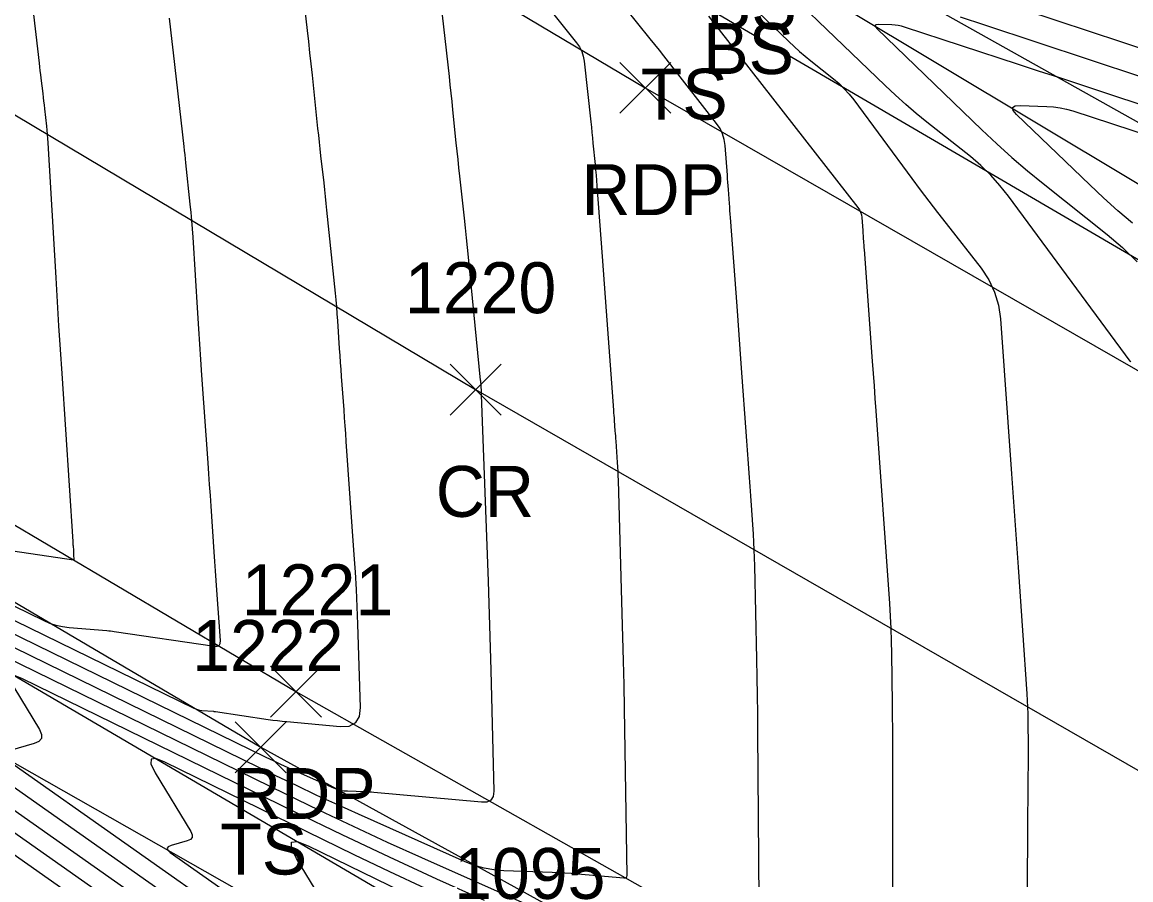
# Model space of a CAD drawing. Extents: x 1650836 to 1652450, y 332578 to 333908.
# Drawn here: x 1651871 to 1651914.59, y 332889.77 to 332923.46 of the extents above; entities that cross this region are included whole.
import ezdxf

# ---------------------------------------------------------------- set-up
doc = ezdxf.new("R2010")
doc.units = 0
for name, color, linetype in [('L_A', 7, 'Continuous'), ('L_I', 7, 'Continuous'), ('L_TIC', 7, 'Continuous'), ('LELB', 7, 'Continuous'), ('LSOGCMA', 7, 'Continuous'), ('LSOGCMI', 7, 'Continuous'), ('P_A', 7, 'Continuous'), ('P_I', 7, 'Continuous'), ('P_TIC', 7, 'Continuous'), ('PET', 7, 'Continuous'), ('PRC', 7, 'Continuous')]:
    doc.layers.add(name, color=color, linetype=linetype)

msp = doc.modelspace()

# ---------------------------------------------------------------- linework, layer by layer
at = {"layer": 'L_TIC'}
for points in [[(1651879.379, 332893.976), (1651881.379, 332895.976)], [(1651881.379, 332893.976), (1651879.379, 332895.976)]]:
    msp.add_lwpolyline(points, dxfattribs=at)
at = {"layer": 'LELB'}
for points in [[(1652004.611, 332876.377), (1652000.575, 332878.245), (1651971.943, 332890.057), (1651931.469, 332910.231), (1651899.444, 332928.179), (1651868.914, 332946.877)], [(1652004.611, 332876.377), (1652004.078, 332874.687), (1651998.585, 332874.498), (1651971.102, 332887.818), (1651930.139, 332907.952), (1651899.336, 332926.423), (1651867.782, 332944.676)], [(1651863.072, 332944.289), (1651896.914, 332924.632), (1651933.94, 332903.012), (1651966.422, 332886.181), (1652000.17, 332869.987)], [(1651844.759, 332915.941), (1651880.379, 332894.976), (1651917.082, 332874.787), (1651949.824, 332853.945), (1651967.074, 332844.342), (1652000.53, 332828.254), (1652035.357, 332809.776), (1652067.23, 332793.489), (1652106.029, 332773.108), (1652143.274, 332753.324), (1652172.167, 332734.049)], [(1652048.756, 332662.461), (1652082.555, 332678.298), (1652130.366, 332703.201), (1652148.083, 332715.406), (1652159.47, 332726.367), (1652148.02, 332734.227), (1652128.413, 332739.339), (1652116.951, 332747.33), (1652106.793, 332756.875), (1652094.604, 332761.138), (1652083.802, 332764.466), (1652074.482, 332770.284), (1652065.17, 332770.428), (1652062.989, 332774.387), (1652054.537, 332784.724), (1652034.993, 332796.475), (1652025.062, 332801.1), (1652009.772, 332808.074), (1651988.967, 332816.401), (1651980.006, 332832.954), (1651960.575, 332843.477), (1651932.852, 332862.75), (1651890.753, 332886.019), (1651847.527, 332911.35)], [(1651992.104, 332790.093), (1651989.915, 332804.738), (1651988.967, 332816.401), (1651977.078, 332830.976), (1651959.162, 332840.786), (1651931.328, 332859.703), (1651889.406, 332883.733), (1651845.231, 332908.813)]]:
    msp.add_lwpolyline(points, dxfattribs=at)
at = {"layer": 'LSOGCMA'}
msp.add_lwpolyline([(1651850.934, 332910.157), (1651871.822, 332899.963), (1651872.07, 332899.856), (1651872.324, 332899.774), (1651872.585, 332899.715), (1651872.852, 332899.681), (1651874.331, 332899.562), (1651874.404, 332899.555), (1651874.477, 332899.547), (1651874.55, 332899.538), (1651874.622, 332899.528), (1651878.561, 332898.943), (1651878.672, 332898.942), (1651878.749, 332898.979), (1651878.791, 332899.053), (1651878.799, 332899.164), (1651878.652, 332901.151), (1651878.625, 332901.525), (1651878.598, 332901.9), (1651878.572, 332902.274), (1651878.547, 332902.649), (1651878.427, 332904.447), (1651878.399, 332904.871), (1651878.37, 332905.295), (1651878.341, 332905.72), (1651878.311, 332906.144), (1651878.069, 332909.598), (1651878.027, 332910.205), (1651877.987, 332910.811), (1651877.947, 332911.417), (1651877.908, 332912.024), (1651877.721, 332915.012), (1651877.699, 332915.337), (1651877.674, 332915.662), (1651877.645, 332915.986), (1651877.612, 332916.31), (1651877.44, 332917.938), (1651877.423, 332918.096), (1651877.406, 332918.254), (1651877.388, 332918.412), (1651877.37, 332918.57), (1651876.946, 332922.249), (1651876.893, 332922.704), (1651876.841, 332923.16), (1651876.79, 332923.615)], dxfattribs=at)
at = {"layer": 'LSOGCMI'}
for points in [[(1651858.348, 332905.977), (1651877.745, 332896.511), (1651877.821, 332896.478), (1651877.899, 332896.453), (1651877.979, 332896.435), (1651878.062, 332896.424), (1651878.517, 332896.388), (1651878.54, 332896.386), (1651878.562, 332896.383), (1651878.584, 332896.381), (1651878.607, 332896.377), (1651880.674, 332896.07), (1651880.856, 332896.044), (1651881.039, 332896.021), (1651881.221, 332896.001), (1651881.404, 332895.983), (1651883.503, 332895.792), (1651883.861, 332895.81), (1651884.113, 332895.942), (1651884.259, 332896.185), (1651884.299, 332896.542), (1651884.197, 332899.811), (1651884.172, 332900.493), (1651884.141, 332901.175), (1651884.103, 332901.857), (1651884.058, 332902.538), (1651883.745, 332906.987), (1651883.723, 332907.297), (1651883.7, 332907.607), (1651883.678, 332907.917), (1651883.655, 332908.227), (1651883.558, 332909.541), (1651883.538, 332909.814), (1651883.518, 332910.087), (1651883.499, 332910.361), (1651883.481, 332910.634), (1651883.408, 332911.728), (1651883.389, 332912.001), (1651883.367, 332912.274), (1651883.343, 332912.547), (1651883.316, 332912.82), (1651882.983, 332916.069), (1651882.955, 332916.338), (1651882.927, 332916.606), (1651882.898, 332916.874), (1651882.868, 332917.142), (1651882.748, 332918.215), (1651882.718, 332918.483), (1651882.688, 332918.751), (1651882.659, 332919.019), (1651882.631, 332919.288), (1651882.41, 332921.38), (1651882.363, 332921.818), (1651882.315, 332922.256), (1651882.266, 332922.694), (1651882.216, 332923.132), (1651881.558, 332928.832)], [(1651889.162, 332927.188), (1651892.797, 332922.652), (1651892.912, 332922.487), (1651893, 332922.311), (1651893.062, 332922.124), (1651893.097, 332921.926), (1651893.356, 332919.546), (1651893.379, 332919.337), (1651893.401, 332919.128), (1651893.422, 332918.918), (1651893.443, 332918.709), (1651893.526, 332917.871), (1651893.547, 332917.661), (1651893.565, 332917.452), (1651893.583, 332917.242), (1651893.599, 332917.032), (1651893.808, 332914.248), (1651893.848, 332913.714), (1651893.888, 332913.18), (1651893.927, 332912.646), (1651893.966, 332912.111), (1651894.248, 332908.213), (1651894.255, 332908.112), (1651894.263, 332908.012), (1651894.27, 332907.911), (1651894.278, 332907.81), (1651894.307, 332907.407), (1651894.315, 332907.307), (1651894.322, 332907.206), (1651894.329, 332907.105), (1651894.337, 332907.005), (1651894.397, 332906.161), (1651894.409, 332905.987), (1651894.418, 332905.812), (1651894.426, 332905.638), (1651894.432, 332905.463), (1651894.582, 332900.226), (1651894.608, 332899.295), (1651894.63, 332898.364), (1651894.649, 332897.433), (1651894.666, 332896.502), (1651894.771, 332889.931), (1651894.765, 332889.883), (1651894.745, 332889.85), (1651894.71, 332889.832), (1651894.661, 332889.829), (1651892.833, 332889.996), (1651892.585, 332890.016), (1651892.335, 332890.034), (1651892.086, 332890.048), (1651891.836, 332890.059), (1651889.942, 332890.126), (1651889.547, 332890.159), (1651889.161, 332890.228), (1651888.784, 332890.335), (1651888.415, 332890.479), (1651884.225, 332892.342), (1651883.407, 332892.71), (1651882.592, 332893.086), (1651881.781, 332893.468), (1651880.973, 332893.859), (1651859.716, 332904.244)], [(1651871.095, 332926.816), (1651871.666, 332921.853), (1651871.684, 332921.703), (1651871.701, 332921.553), (1651871.719, 332921.403), (1651871.737, 332921.254), (1651871.808, 332920.655), (1651871.825, 332920.505), (1651871.843, 332920.356), (1651871.86, 332920.206), (1651871.877, 332920.056), (1651871.953, 332919.377), (1651871.97, 332919.213), (1651871.985, 332919.05), (1651871.998, 332918.886), (1651872.009, 332918.723), (1651872.32, 332913.414), (1651872.376, 332912.474), (1651872.434, 332911.535), (1651872.493, 332910.596), (1651872.554, 332909.657), (1651872.991, 332903.054), (1651872.993, 332903.011), (1651872.996, 332902.968), (1651872.999, 332902.925), (1651873.002, 332902.882), (1651873.013, 332902.7), (1651873.015, 332902.662), (1651873.018, 332902.624), (1651873.02, 332902.587), (1651873.023, 332902.549), (1651873.038, 332902.34), (1651873.037, 332902.332), (1651873.034, 332902.327), (1651873.029, 332902.325), (1651873.021, 332902.325), (1651870.638, 332902.679)], [(1651914.59, 332910.112), (1651914.567, 332910.143), (1651909.779, 332916.622), (1651909.443, 332917.047), (1651909.081, 332917.448), (1651908.693, 332917.824), (1651908.279, 332918.176), (1651906.574, 332919.532), (1651906.152, 332919.876), (1651905.739, 332920.229), (1651905.333, 332920.592), (1651904.936, 332920.965), (1651899.332, 332926.353)], [(1651916.252, 332922.004), (1651914.233, 332922.676), (1651902.789, 332926.46)], [(1651887.293, 332925.694), (1651887.782, 332921.328), (1651887.818, 332921.002), (1651887.854, 332920.675), (1651887.888, 332920.349), (1651887.922, 332920.022), (1651888.056, 332918.715), (1651888.09, 332918.388), (1651888.124, 332918.061), (1651888.159, 332917.735), (1651888.194, 332917.408), (1651888.374, 332915.758), (1651888.415, 332915.374), (1651888.455, 332914.99), (1651888.495, 332914.606), (1651888.534, 332914.222), (1651889.012, 332909.402), (1651889.014, 332909.381), (1651889.016, 332909.36), (1651889.018, 332909.339), (1651889.019, 332909.318), (1651889.027, 332909.212), (1651889.032, 332909.149), (1651889.045, 332908.972), (1651889.047, 332908.936), (1651889.049, 332908.899), (1651889.051, 332908.863), (1651889.053, 332908.826), (1651889.32, 332901.498), (1651889.35, 332900.625), (1651889.378, 332899.752), (1651889.403, 332898.879), (1651889.425, 332898.006), (1651889.538, 332893.256), (1651889.512, 332893.045), (1651889.425, 332892.901), (1651889.275, 332892.823), (1651889.063, 332892.812), (1651884.825, 332893.198), (1651884.737, 332893.205), (1651884.648, 332893.212), (1651884.559, 332893.217), (1651884.469, 332893.22), (1651883.793, 332893.245), (1651883.652, 332893.256), (1651883.514, 332893.281), (1651883.38, 332893.319), (1651883.248, 332893.37), (1651881.752, 332894.036), (1651881.46, 332894.167), (1651881.169, 332894.301), (1651880.879, 332894.438), (1651880.591, 332894.577), (1651854.082, 332907.528)], [(1651899.994, 332887.267), (1651899.925, 332895.585), (1651899.918, 332896.3), (1651899.909, 332897.014), (1651899.897, 332897.728), (1651899.883, 332898.442), (1651899.807, 332902.101), (1651899.799, 332902.413), (1651899.786, 332902.725), (1651899.77, 332903.037), (1651899.75, 332903.348), (1651899.643, 332904.857), (1651899.631, 332905.036), (1651899.618, 332905.216), (1651899.605, 332905.395), (1651899.592, 332905.574), (1651899.539, 332906.291), (1651899.526, 332906.471), (1651899.513, 332906.65), (1651899.5, 332906.829), (1651899.488, 332907.008), (1651899.27, 332910.045), (1651899.23, 332910.611), (1651899.189, 332911.177), (1651899.147, 332911.743), (1651899.106, 332912.309), (1651898.848, 332915.784), (1651898.838, 332915.923), (1651898.828, 332916.061), (1651898.818, 332916.2), (1651898.808, 332916.338), (1651898.768, 332916.892), (1651898.758, 332917.03), (1651898.747, 332917.168), (1651898.737, 332917.307), (1651898.727, 332917.445), (1651898.639, 332918.616), (1651898.605, 332918.851), (1651898.537, 332919.074), (1651898.437, 332919.284), (1651898.305, 332919.481), (1651896.409, 332921.906), (1651896.232, 332922.132), (1651896.054, 332922.357), (1651895.875, 332922.582), (1651895.696, 332922.807), (1651893.271, 332925.833)], [(1651899.014, 332924.744), (1651901.14, 332922.7), (1651901.349, 332922.504), (1651901.563, 332922.312), (1651901.781, 332922.126), (1651902.003, 332921.945), (1651902.901, 332921.23), (1651903.119, 332921.045), (1651903.324, 332920.847), (1651903.514, 332920.636), (1651903.692, 332920.412), (1651905.98, 332917.316), (1651906.312, 332916.869), (1651906.647, 332916.425), (1651906.986, 332915.983), (1651907.327, 332915.544), (1651908.698, 332913.79), (1651909.003, 332913.337), (1651909.232, 332912.855), (1651909.385, 332912.344), (1651909.462, 332911.803), (1651909.896, 332905.722), (1651909.961, 332904.805), (1651910.026, 332903.888), (1651910.09, 332902.971), (1651910.155, 332902.054), (1651910.501, 332897.08), (1651910.517, 332896.815), (1651910.529, 332896.551), (1651910.537, 332896.286), (1651910.541, 332896.022), (1651910.546, 332894.962), (1651910.547, 332894.697), (1651910.547, 332894.433), (1651910.546, 332894.168), (1651910.544, 332893.903), (1651910.525, 332891.388), (1651910.521, 332890.881), (1651910.518, 332890.373), (1651910.516, 332889.866), (1651910.514, 332889.359)], [(1651897.979, 332923.7), (1651903.86, 332916.176), (1651903.919, 332916.088), (1651903.964, 332915.995), (1651903.994, 332915.896), (1651904.009, 332915.792), (1651904.047, 332915.271), (1651904.052, 332915.209), (1651904.056, 332915.148), (1651904.061, 332915.087), (1651904.065, 332915.025), (1651904.083, 332914.78), (1651904.087, 332914.719), (1651904.092, 332914.658), (1651904.096, 332914.596), (1651904.101, 332914.535), (1651904.422, 332910.142), (1651904.457, 332909.656), (1651904.492, 332909.169), (1651904.527, 332908.682), (1651904.562, 332908.196), (1651905.097, 332900.62), (1651905.128, 332900.129), (1651905.152, 332899.638), (1651905.169, 332899.146), (1651905.179, 332898.654), (1651905.204, 332896.686), (1651905.21, 332896.194), (1651905.214, 332895.702), (1651905.216, 332895.21), (1651905.217, 332894.718), (1651905.219, 332889.324)], [(1651907.881, 332923.668), (1651908.829, 332923.355), (1651917.063, 332920.633)], [(1651919.893, 332918.59), (1651913.326, 332920.761), (1651912.539, 332921.021), (1651911.752, 332921.28), (1651910.964, 332921.538), (1651910.177, 332921.796), (1651905.694, 332923.262), (1651905.571, 332923.297), (1651905.447, 332923.324), (1651905.321, 332923.341), (1651905.193, 332923.349), (1651904.68, 332923.364), (1651904.58, 332923.357), (1651904.534, 332923.326), (1651904.544, 332923.271), (1651904.609, 332923.194), (1651908.733, 332919.23), (1651909.317, 332918.681), (1651909.914, 332918.146), (1651910.524, 332917.625), (1651911.145, 332917.119), (1651913.657, 332915.121), (1651914.267, 332914.603), (1651914.838, 332914.049)], [(1651914.652, 332915.563), (1651914.08, 332916.052), (1651913.52, 332916.554), (1651912.972, 332917.069), (1651910.094, 332919.835), (1651909.962, 332919.993), (1651909.942, 332920.104), (1651910.035, 332920.167), (1651910.24, 332920.183), (1651911.287, 332920.152), (1651911.547, 332920.135), (1651911.804, 332920.1), (1651912.058, 332920.046), (1651912.308, 332919.974), (1651915.382, 332918.969)], [(1651912.399, 332858.755), (1651909.768, 332860.822), (1651908.772, 332861.604), (1651907.776, 332862.385), (1651906.781, 332863.167), (1651905.785, 332863.948), (1651890.033, 332876.308), (1651888.97, 332877.141), (1651887.906, 332877.974), (1651886.841, 332878.805), (1651885.776, 332879.636), (1651881.513, 332882.958), (1651880.442, 332883.781), (1651879.362, 332884.592), (1651878.272, 332885.389), (1651877.172, 332886.173), (1651849.359, 332905.751)], [(1651851.136, 332905.867), (1651851.012, 332905.705), (1651851.086, 332905.478), (1651851.378, 332905.214), (1651878.925, 332885.824), (1651879.867, 332885.152), (1651880.801, 332884.469), (1651881.727, 332883.774), (1651882.644, 332883.069), (1651886.296, 332880.223), (1651887.209, 332879.511), (1651888.121, 332878.799), (1651889.032, 332878.086), (1651889.943, 332877.372), (1651902.25, 332867.715), (1651903.697, 332866.58), (1651905.144, 332865.444), (1651906.591, 332864.308), (1651908.038, 332863.172), (1651913.05, 332859.236)], [(1651857.738, 332901.621), (1651880.678, 332885.474)], [(1651882.431, 332885.124), (1651864.098, 332898.029), (1651863.904, 332898.204), (1651863.855, 332898.355), (1651863.951, 332898.481), (1651864.192, 332898.583), (1651865.481, 332898.949), (1651865.721, 332899.056), (1651865.847, 332899.208), (1651865.858, 332899.405), (1651865.755, 332899.646), (1651865.114, 332900.703), (1651865.009, 332900.917), (1651865.013, 332901.031), (1651865.126, 332901.046), (1651865.349, 332900.96), (1651881.355, 332893.14), (1651882.683, 332892.499), (1651884.016, 332891.87), (1651885.354, 332891.253), (1651886.698, 332890.648), (1651893.59, 332887.584)], [(1651889.172, 332888.954), (1651887.301, 332889.796), (1651885.439, 332890.654), (1651883.585, 332891.529), (1651881.738, 332892.421), (1651870.983, 332897.676), (1651870.689, 332897.789), (1651870.54, 332897.77), (1651870.535, 332897.619), (1651870.674, 332897.338), (1651871.685, 332895.669), (1651871.767, 332895.478), (1651871.758, 332895.323), (1651871.658, 332895.202), (1651871.469, 332895.118), (1651870.529, 332894.851), (1651870.348, 332894.775), (1651870.276, 332894.68), (1651870.313, 332894.567), (1651870.458, 332894.436), (1651884.184, 332884.775)], [(1651886.854, 332889.421), (1651885.454, 332890.082), (1651884.059, 332890.755), (1651876.616, 332894.392), (1651876.253, 332894.532), (1651876.067, 332894.508), (1651876.061, 332894.322), (1651876.233, 332893.972), (1651877.633, 332891.663), (1651877.688, 332891.536), (1651877.682, 332891.432), (1651877.616, 332891.352), (1651877.49, 332891.296), (1651876.865, 332891.119), (1651876.745, 332891.068), (1651876.697, 332891.006), (1651876.722, 332890.931), (1651876.818, 332890.843), (1651885.936, 332884.425)], [(1651883.582, 332887.656), (1651881.792, 332890.607), (1651881.587, 332891.024), (1651881.595, 332891.247), (1651881.816, 332891.275), (1651882.25, 332891.108), (1651886.488, 332889.037)]]:
    msp.add_lwpolyline(points, dxfattribs=at)
at = {"layer": 'P_TIC'}
for points in [[(1651894.497, 332919.881), (1651896.497, 332921.881)], [(1651896.497, 332919.881), (1651894.497, 332921.881)], [(1651887.829, 332908.027), (1651889.829, 332910.027)], [(1651889.829, 332908.027), (1651887.829, 332910.027)], [(1651880.765, 332896.162), (1651882.765, 332898.162)], [(1651882.765, 332896.162), (1651880.765, 332898.162)]]:
    msp.add_lwpolyline(points, dxfattribs=at)
at = {"layer": 'PET'}
for points in [[(1651782.185, 332994.087), (1651800.504, 332980.945), (1651823.969, 332965.234), (1651861.092, 332941.311), (1651895.497, 332920.881), (1651932.1, 332899.878), (1651964.344, 332882.546), (1651997.084, 332865.287), (1652030.302, 332847.665), (1652049.548, 332837.673), (1652081.974, 332820.953), (1652121.026, 332800.401), (1652157.819, 332781.161), (1652191.945, 332763.077), (1652232.596, 332742.33), (1652251.93, 332731.59), (1652295.202, 332708.727), (1652345.726, 332682.336), (1652379.152, 332664.868), (1652402.111, 332652.828)], [(1651764.546, 332972.615), (1651784.506, 332958.597), (1651809.702, 332941.927), (1651846.26, 332918.158), (1651881.765, 332897.162), (1651918.116, 332876.642), (1651951.432, 332858.415), (1651975.296, 332845.48), (1652002.223, 332831.337), (1652037.173, 332813.417), (1652069.296, 332796.636), (1652107.428, 332776.545), (1652145.079, 332756.921), (1652175.234, 332740.226), (1652190.754, 332731.861), (1652206.573, 332723.523), (1652239.422, 332706.921), (1652282.404, 332684.366), (1652332.494, 332658.525), (1652365.542, 332641.171), (1652388.914, 332629.021)]]:
    msp.add_lwpolyline(points, dxfattribs=at)
at = {"layer": 'PRC'}
msp.add_lwpolyline([(1651773.612, 332982.822), (1651792.672, 332969.525), (1651816.542, 332953.47), (1651853.779, 332929.89), (1651888.829, 332909.027), (1651925.09, 332888.189), (1651957.726, 332870.48), (1651982.519, 332857.297), (1652019.654, 332837.681), (1652042.767, 332825.192), (1652076.048, 332808.311), (1652114.48, 332787.851), (1652150.944, 332769.103), (1652185.791, 332750.516), (1652225.777, 332729.89), (1652246.28, 332718.635), (1652288.707, 332696.529), (1652339.002, 332669.86), (1652372.556, 332652.699), (1652395.364, 332640.33)], dxfattribs=at)

# ---------------------------------------------------------------- texts
at = {"layer": 'L_A'}
for s, p in [('BS', (1651897.885, 332923.179)), ('BS', (1651897.777, 332921.423)), ('TS', (1651895.323, 332919.632)), ('TS', (1651878.788, 332889.976))]:
    msp.add_text(s, height=2, dxfattribs=at).set_placement(p)
at = {"layer": 'L_I'}
for s, p in [('1222', (1651877.686, 332897.976)), ('1095', (1651887.982, 332889.019))]:
    msp.add_text(s, height=2, dxfattribs=at).set_placement(p)
at = {"layer": 'P_A'}
for s, p in [('RDP', (1651892.985, 332915.881)), ('CR', (1651887.262, 332904.027)), ('RDP', (1651879.253, 332892.162))]:
    msp.add_text(s, height=2, dxfattribs=at).set_placement(p)
at = {"layer": 'P_I'}
for s, p in [('1220', (1651886.049, 332912.027)), ('1221', (1651879.639, 332900.162))]:
    msp.add_text(s, height=2, dxfattribs=at).set_placement(p)

doc.saveas('drawing.dxf')
